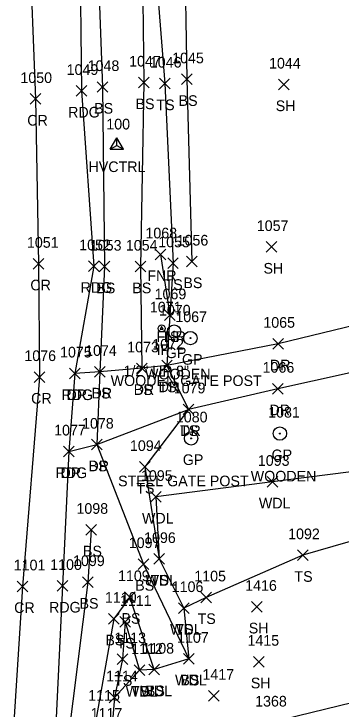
# Model space of a CAD drawing. Extents: x 1678553 to 1680768, y 787260 to 792325.
# Drawn here: x 1678701.2 to 1678762.7, y 787588.2 to 787718.8 of the extents above; entities that cross this region are included whole.
import ezdxf

# ---------------------------------------------------------------- set-up
doc = ezdxf.new("R2010")
doc.units = 0
for name, color, linetype in [('C_A', 7, 'Continuous'), ('C_I', 7, 'Continuous'), ('CPSM', 7, 'Continuous'), ('L_A', 7, 'Continuous'), ('L_I', 7, 'Continuous'), ('L_TIC', 7, 'Continuous'), ('LAWA', 7, 'Continuous'), ('LAWE', 7, 'Continuous'), ('LELB', 7, 'Continuous'), ('LFNC', 7, 'Continuous'), ('M_A', 7, 'Continuous'), ('M_C', 7, 'Continuous'), ('M_I', 7, 'Continuous'), ('MPIR', 7, 'Continuous'), ('P_A', 7, 'Continuous'), ('P_I', 7, 'Continuous'), ('P_TIC', 7, 'Continuous'), ('PEU', 7, 'Continuous'), ('PRC', 7, 'Continuous'), ('R_A', 7, 'Continuous'), ('R_C', 7, 'Continuous'), ('R_I', 7, 'Continuous'), ('R_TIC', 7, 'Continuous'), ('RDP', 7, 'Continuous'), ('RGP', 7, 'Continuous')]:
    doc.layers.add(name, color=color, linetype=linetype)

msp = doc.modelspace()

# ---------------------------------------------------------------- linework, layer by layer
at = {"layer": 'CPSM'}
for p, q in [((1678719.31, 787693.37), (1678720.56, 787695.53)), ((1678721.81, 787693.37), (1678720.56, 787695.53)), ((1678720.56, 787694.09), (1678720.56, 787695.53)), ((1678719.31, 787693.37), (1678720.56, 787694.09)), ((1678719.31, 787693.37), (1678721.81, 787693.37)), ((1678720.56, 787694.09), (1678720.56, 787694.09)), ((1678720.56, 787694.09), (1678721.81, 787693.37))]:
    msp.add_line(p, q, dxfattribs=at)
at = {"layer": 'L_TIC'}
for points in [[(1678724.65, 787704.9), (1678726.65, 787706.9)], [(1678726.65, 787704.9), (1678724.65, 787706.9)], [(1678728.61, 787704.71), (1678730.61, 787706.71)], [(1678730.61, 787704.71), (1678728.61, 787706.71)], [(1678732.74, 787705.51), (1678734.74, 787707.51)], [(1678734.74, 787705.51), (1678732.74, 787707.51)], [(1678750.94, 787704.53), (1678752.94, 787706.53)], [(1678752.94, 787704.53), (1678750.94, 787706.53)], [(1678716.88, 787704.06), (1678718.88, 787706.06)], [(1678718.88, 787704.06), (1678716.88, 787706.06)], [(1678748.64, 787674.02), (1678750.64, 787676.02)], [(1678750.64, 787674.02), (1678748.64, 787676.02)], [(1678727.77, 787672.63), (1678729.77, 787674.63)], [(1678729.77, 787672.63), (1678727.77, 787674.63)], [(1678730.13, 787670.96), (1678732.13, 787672.96)], [(1678732.13, 787670.96), (1678730.13, 787672.96)], [(1678733.64, 787671.29), (1678735.64, 787673.29)], [(1678735.64, 787671.29), (1678733.64, 787673.29)], [(1678717.28, 787670.33), (1678719.28, 787672.33)], [(1678719.28, 787670.33), (1678717.28, 787672.33)], [(1678724.04, 787670.33), (1678726.04, 787672.33)], [(1678726.04, 787670.33), (1678724.04, 787672.33)], [(1678729.51, 787661.19), (1678731.51, 787663.19)], [(1678731.51, 787661.19), (1678729.51, 787663.19)], [(1678729.51, 787661.19), (1678731.51, 787663.19)], [(1678731.51, 787661.19), (1678729.51, 787663.19)], [(1678724.3, 787651.23), (1678726.3, 787653.23)], [(1678726.3, 787651.23), (1678724.3, 787653.23)], [(1678729, 787651.74), (1678731, 787653.74)], [(1678731, 787651.74), (1678729, 787653.74)], [(1678716.39, 787650.57), (1678718.39, 787652.57)], [(1678718.39, 787650.57), (1678716.39, 787652.57)], [(1678733.05, 787643.53), (1678735.05, 787645.53)], [(1678735.05, 787643.53), (1678733.05, 787645.53)], [(1678715.82, 787636.9), (1678717.82, 787638.9)], [(1678717.82, 787636.9), (1678715.82, 787638.9)], [(1678724.82, 787632.71), (1678726.82, 787634.71)], [(1678726.82, 787632.71), (1678724.82, 787634.71)], [(1678748.84, 787629.92), (1678750.84, 787631.92)], [(1678750.84, 787629.92), (1678748.84, 787631.92)], [(1678726.88, 787627.09), (1678728.88, 787629.09)], [(1678728.88, 787627.09), (1678726.88, 787629.09)], [(1678714.77, 787620.91), (1678716.77, 787622.91)], [(1678716.77, 787620.91), (1678714.77, 787622.91)], [(1678754.53, 787616.14), (1678756.53, 787618.14)], [(1678756.53, 787616.14), (1678754.53, 787618.14)], [(1678724.59, 787614.48), (1678726.59, 787616.48)], [(1678726.59, 787614.48), (1678724.59, 787616.48)], [(1678724.59, 787614.48), (1678726.59, 787616.48)], [(1678726.59, 787614.48), (1678724.59, 787616.48)], [(1678727.53, 787615.43), (1678729.53, 787617.43)], [(1678729.53, 787615.43), (1678727.53, 787617.43)], [(1678727.53, 787615.43), (1678729.53, 787617.43)], [(1678729.53, 787615.43), (1678727.53, 787617.43)], [(1678714.13, 787611.1), (1678716.13, 787613.1)], [(1678716.13, 787611.1), (1678714.13, 787613.1)], [(1678722.01, 787608.27), (1678724.01, 787610.27)], [(1678724.01, 787608.27), (1678722.01, 787610.27)], [(1678736.34, 787608.22), (1678738.34, 787610.22)], [(1678738.34, 787608.22), (1678736.34, 787610.22)], [(1678745.87, 787606.45), (1678747.87, 787608.45)], [(1678747.87, 787606.45), (1678745.87, 787608.45)], [(1678732.15, 787606.22), (1678734.15, 787608.22)], [(1678734.15, 787606.22), (1678732.15, 787608.22)], [(1678732.15, 787606.22), (1678734.15, 787608.22)], [(1678734.15, 787606.22), (1678732.15, 787608.22)], [(1678718.99, 787604.2), (1678720.99, 787606.2)], [(1678720.99, 787604.2), (1678718.99, 787606.2)], [(1678721.14, 787603.62), (1678723.14, 787605.62)], [(1678723.14, 787603.62), (1678721.14, 787605.62)], [(1678721.14, 787603.62), (1678723.14, 787605.62)], [(1678723.14, 787603.62), (1678721.14, 787605.62)], [(1678720.67, 787596.62), (1678722.67, 787598.62)], [(1678722.67, 787596.62), (1678720.67, 787598.62)], [(1678733.09, 787596.69), (1678735.09, 787598.69)], [(1678735.09, 787596.69), (1678733.09, 787598.69)], [(1678733.09, 787596.69), (1678735.09, 787598.69)], [(1678735.09, 787596.69), (1678733.09, 787598.69)], [(1678746.25, 787596.14), (1678748.25, 787598.14)], [(1678748.25, 787596.14), (1678746.25, 787598.14)], [(1678723.83, 787594.57), (1678725.83, 787596.57)], [(1678725.83, 787594.57), (1678723.83, 787596.57)], [(1678723.83, 787594.57), (1678725.83, 787596.57)], [(1678725.83, 787594.57), (1678723.83, 787596.57)], [(1678726.59, 787594.66), (1678728.59, 787596.66)], [(1678728.59, 787594.66), (1678726.59, 787596.66)], [(1678726.59, 787594.66), (1678728.59, 787596.66)], [(1678728.59, 787594.66), (1678726.59, 787596.66)], [(1678737.79, 787589.75), (1678739.79, 787591.75)], [(1678739.79, 787589.75), (1678737.79, 787591.75)], [(1678719.12, 787589.44), (1678721.12, 787591.44)], [(1678721.12, 787589.44), (1678719.12, 787591.44)], [(1678719.12, 787589.44), (1678721.12, 787591.44)], [(1678721.12, 787589.44), (1678719.12, 787591.44)]]:
    msp.add_lwpolyline(points, dxfattribs=at)
at = {"layer": 'LAWA'}
msp.add_lwpolyline([(1678789.66, 787618.55), (1678782.28, 787633.91), (1678770.99, 787633.61), (1678749.84, 787630.92), (1678727.88, 787628.09), (1678728.53, 787616.43), (1678733.15, 787607.22), (1678734.09, 787597.69), (1678727.59, 787595.66), (1678724.83, 787595.57), (1678720.12, 787590.44), (1678719.43, 787582.2)], dxfattribs=at)
at = {"layer": 'LAWE'}
msp.add_lwpolyline([(1678722.67, 787582.69), (1678729.64, 787581.87), (1678749.3, 787585.72), (1678767.55, 787590.14), (1678784.53, 787599.95), (1678818.4, 787617.01)], dxfattribs=at)
at = {"layer": 'LELB'}
for points in [[(1678709.4, 787836.24), (1678712.41, 787802.3), (1678715.2, 787769.05), (1678716.9, 787732.18), (1678717.88, 787705.06), (1678718.28, 787671.33), (1678717.39, 787651.57), (1678716.82, 787637.9), (1678725.59, 787615.48)], [(1678711.45, 787836.11), (1678718.36, 787803.19), (1678726.6, 787769.62), (1678727.53, 787731.61), (1678729.61, 787705.71), (1678731.13, 787671.96), (1678730.51, 787662.19), (1678730, 787652.74), (1678734.05, 787644.53), (1678725.82, 787633.71), (1678728.53, 787616.43)], [(1678717.2, 787799.09), (1678720.39, 787781.96), (1678724.18, 787769.78), (1678725.32, 787731.66), (1678725.65, 787705.9), (1678725.04, 787671.33), (1678725.3, 787652.23)], [(1678731.19, 787767.04), (1678733.28, 787732.25), (1678733.74, 787706.51), (1678734.64, 787672.29)], [(1678817.97, 787629.35), (1678796.25, 787621.01), (1678789.66, 787618.55), (1678772.84, 787622.13), (1678755.53, 787617.14), (1678737.34, 787609.22), (1678733.15, 787607.22)], [(1678715.77, 787621.91), (1678715.13, 787612.1), (1678711.4, 787582.3), (1678709.58, 787571.68), (1678707.82, 787563.26)], [(1678725.59, 787615.48), (1678734.09, 787597.69)], [(1678727.59, 787595.66), (1678723.01, 787609.27), (1678719.99, 787605.2), (1678716.76, 787586.82), (1678717.22, 787583.43), (1678719.43, 787582.2)], [(1678722.14, 787604.62), (1678721.67, 787597.62), (1678720.12, 787590.44)], [(1678722.14, 787604.62), (1678724.83, 787595.57)]]:
    msp.add_lwpolyline(points, dxfattribs=at)
at = {"layer": 'LFNC'}
msp.add_lwpolyline([(1678728.77, 787673.63), (1678730.51, 787662.19)], dxfattribs=at)
at = {"layer": 'MPIR'}
msp.add_lwpolyline([(1678728.99, 787660.06), (1678728.7, 787659.56), (1678729.28, 787659.56)], close=True, dxfattribs=at)
msp.add_circle((1678728.99, 787659.73), 0.667, dxfattribs=at)
at = {"layer": 'P_TIC'}
for points in [[(1678712.93, 787703.33), (1678714.93, 787705.33)], [(1678714.93, 787703.33), (1678712.93, 787705.33)], [(1678704.32, 787701.81), (1678706.32, 787703.81)], [(1678706.32, 787701.81), (1678704.32, 787703.81)], [(1678704.89, 787670.87), (1678706.89, 787672.87)], [(1678706.89, 787670.87), (1678704.89, 787672.87)], [(1678715.28, 787670.41), (1678717.28, 787672.41)], [(1678717.28, 787670.41), (1678715.28, 787672.41)], [(1678705.04, 787649.6), (1678707.04, 787651.6)], [(1678707.04, 787649.6), (1678705.04, 787651.6)], [(1678711.68, 787650.27), (1678713.68, 787652.27)], [(1678713.68, 787650.27), (1678711.68, 787652.27)], [(1678710.57, 787635.62), (1678712.57, 787637.62)], [(1678712.57, 787635.62), (1678710.57, 787637.62)], [(1678709.35, 787610.37), (1678711.35, 787612.37)], [(1678711.35, 787610.37), (1678709.35, 787612.37)], [(1678701.84, 787610.29), (1678703.84, 787612.29)], [(1678703.84, 787610.29), (1678701.84, 787612.29)]]:
    msp.add_lwpolyline(points, dxfattribs=at)
at = {"layer": 'PEU'}
msp.add_lwpolyline([(1678707.07, 787835.6), (1678708.87, 787801.61), (1678711.16, 787769.03), (1678713.63, 787732.08), (1678713.93, 787704.33), (1678716.28, 787671.41), (1678712.68, 787651.27), (1678711.57, 787636.62), (1678710.35, 787611.37), (1678708.98, 787582.71), (1678707.82, 787563.26), (1678700.14, 787562.55), (1678691.17, 787560.92)], dxfattribs=at)
at = {"layer": 'PRC'}
msp.add_lwpolyline([(1678698.82, 787835.52), (1678700.15, 787799.39), (1678701.73, 787769.29), (1678704.12, 787733.19), (1678705.32, 787702.81), (1678705.89, 787671.87), (1678706.04, 787650.6), (1678702.84, 787611.29), (1678700.91, 787580.88), (1678700.14, 787562.55)], dxfattribs=at)
at = {"layer": 'R_TIC'}
for points in [[(1678749.91, 787655.85), (1678751.91, 787657.85)], [(1678751.91, 787655.85), (1678749.91, 787657.85)], [(1678724.3, 787651.23), (1678726.3, 787653.23)], [(1678726.3, 787651.23), (1678724.3, 787653.23)], [(1678729, 787651.74), (1678731, 787653.74)], [(1678731, 787651.74), (1678729, 787653.74)], [(1678711.68, 787650.27), (1678713.68, 787652.27)], [(1678713.68, 787650.27), (1678711.68, 787652.27)], [(1678716.39, 787650.57), (1678718.39, 787652.57)], [(1678718.39, 787650.57), (1678716.39, 787652.57)], [(1678749.83, 787647.41), (1678751.83, 787649.41)], [(1678751.83, 787647.41), (1678749.83, 787649.41)], [(1678733.05, 787643.53), (1678735.05, 787645.53)], [(1678735.05, 787643.53), (1678733.05, 787645.53)], [(1678733.05, 787643.53), (1678735.05, 787645.53)], [(1678735.05, 787643.53), (1678733.05, 787645.53)], [(1678715.82, 787636.9), (1678717.82, 787638.9)], [(1678717.82, 787636.9), (1678715.82, 787638.9)], [(1678710.57, 787635.62), (1678712.57, 787637.62)], [(1678712.57, 787635.62), (1678710.57, 787637.62)]]:
    msp.add_lwpolyline(points, dxfattribs=at)
at = {"layer": 'RDP'}
for points in [[(1678806.83, 787669.51), (1678782.39, 787664.49), (1678750.91, 787656.85), (1678730, 787652.74), (1678725.3, 787652.23), (1678717.39, 787651.57), (1678712.68, 787651.27)], [(1678810.64, 787662.52), (1678784.51, 787655.8), (1678750.83, 787648.41), (1678734.05, 787644.53)], [(1678711.57, 787636.62), (1678716.82, 787637.9), (1678734.05, 787644.53)]]:
    msp.add_lwpolyline(points, dxfattribs=at)
at = {"layer": 'RGP'}
for p, q in [((1678731.34, 787659.15), (1678731.34, 787659.15)), ((1678734.39, 787657.91), (1678734.39, 787657.91)), ((1678751.21, 787639.98), (1678751.21, 787639.98)), ((1678734.53, 787639.08), (1678734.53, 787639.08))]:
    msp.add_line(p, q, dxfattribs=at)
for centre, radius in [((1678731.34, 787659.15), 1.25), ((1678731.34, 787659.15), 0.0833), ((1678734.39, 787657.91), 1.25), ((1678734.39, 787657.91), 0.0833), ((1678751.21, 787639.98), 1.25), ((1678734.53, 787639.08), 1.25), ((1678751.21, 787639.98), 0.0833), ((1678734.53, 787639.08), 0.0833)]:
    msp.add_circle(centre, radius, dxfattribs=at)

# ---------------------------------------------------------------- texts
at = {"layer": 'C_A'}
msp.add_text('HVCTRL', height=2, dxfattribs=at).set_placement((1678715.26, 787689.09))
at = {"layer": 'C_I'}
msp.add_text('100', height=2, dxfattribs=at).set_placement((1678718.6, 787697.09))
at = {"layer": 'L_A'}
for s, p in [('BS', (1678724.09, 787700.9)), ('TS', (1678728.02, 787700.71)), ('BS', (1678732.18, 787701.51)), ('SH', (1678750.43, 787700.53)), ('BS', (1678716.32, 787700.06)), ('SH', (1678748.13, 787670.02)), ('FNR', (1678726.31, 787668.63)), ('TS', (1678729.54, 787666.96)), ('BS', (1678733.08, 787667.29)), ('BS', (1678716.72, 787666.33)), ('BS', (1678723.48, 787666.33)), ('FNR', (1678728.04, 787657.19)), ('TS', (1678728.92, 787657.19)), ('BS', (1678723.74, 787647.23)), ('TS', (1678728.41, 787647.74)), ('BS', (1678715.83, 787646.57)), ('TS', (1678732.46, 787639.53)), ('BS', (1678715.26, 787632.9)), ('TS', (1678724.23, 787628.71)), ('WDL', (1678747.26, 787625.92)), ('WDL', (1678725.3, 787623.09)), ('BS', (1678714.21, 787616.91)), ('TS', (1678753.94, 787612.14)), ('BS', (1678724.03, 787610.48)), ('BS', (1678724.03, 787610.48)), ('WDL', (1678725.95, 787611.43)), ('TS', (1678726.94, 787611.43)), ('BS', (1678713.57, 787607.1)), ('BS', (1678721.45, 787604.27)), ('TS', (1678735.75, 787604.22)), ('WDL', (1678730.57, 787602.22)), ('TS', (1678731.56, 787602.22)), ('SH', (1678745.36, 787602.45)), ('BS', (1678718.43, 787600.2)), ('TS', (1678720.55, 787599.62)), ('TS', (1678720.55, 787599.62)), ('TS', (1678720.08, 787592.62)), ('WDL', (1678731.51, 787592.69)), ('BS', (1678732.53, 787592.69)), ('SH', (1678745.74, 787592.14)), ('WDL', (1678722.25, 787590.57)), ('TS', (1678723.24, 787590.57)), ('WDL', (1678725, 787590.66)), ('BS', (1678726.03, 787590.66))]:
    msp.add_text(s, height=2, dxfattribs=at).set_placement(p)
at = {"layer": 'L_I'}
for s, p in [('1047', (1678722.88, 787708.9)), ('1046', (1678726.78, 787708.71)), ('1045', (1678730.97, 787709.51)), ('1044', (1678749.17, 787708.53)), ('1048', (1678715.1, 787708.06)), ('1057', (1678746.87, 787678.02)), ('1068', (1678725.95, 787676.63)), ('1053', (1678715.51, 787674.33)), ('1054', (1678722.27, 787674.33)), ('1055', (1678728.36, 787674.96)), ('1056', (1678731.81, 787675.29)), ('1069', (1678727.68, 787665.19)), ('1069', (1678727.68, 787665.19)), ('1073', (1678722.53, 787655.23)), ('1072', (1678727.23, 787655.74)), ('1074', (1678714.62, 787654.57)), ('1079', (1678731.27, 787647.53)), ('1078', (1678714.05, 787640.9)), ('1094', (1678723.04, 787636.71)), ('1093', (1678747.07, 787633.92)), ('1095', (1678725.11, 787631.09)), ('1098', (1678712.99, 787624.91)), ('1092', (1678752.76, 787620.14)), ('1097', (1678722.82, 787618.48)), ('1097', (1678722.82, 787618.48)), ('1096', (1678725.7, 787619.43)), ('1096', (1678725.7, 787619.43)), ('1099', (1678712.35, 787615.1)), ('1109', (1678720.8, 787612.27)), ('1105', (1678735.13, 787612.22)), ('1416', (1678744.69, 787610.45)), ('1106', (1678730.89, 787610.22)), ('1106', (1678730.89, 787610.22)), ('1110', (1678718.34, 787608.2)), ('1111', (1678721.15, 787607.62)), ('1111', (1678721.15, 787607.62)), ('1113', (1678720.12, 787600.62)), ('1107', (1678731.89, 787600.69)), ('1107', (1678731.89, 787600.69)), ('1415', (1678745.12, 787600.14)), ('1108', (1678725.38, 787598.66)), ('1108', (1678725.38, 787598.66)), ('1112', (1678723.27, 787598.57)), ('1112', (1678723.27, 787598.57)), ('1114', (1678718.56, 787593.44)), ('1114', (1678718.56, 787593.44)), ('1417', (1678736.66, 787593.75)), ('1115', (1678715.2, 787589.82)), ('1368', (1678746.56, 787588.72)), ('1117', (1678715.66, 787586.43))]:
    msp.add_text(s, height=2, dxfattribs=at).set_placement(p)
at = {"layer": 'M_A'}
msp.add_text('IP', height=2, dxfattribs=at).set_placement((1678728.04, 787654.73))
at = {"layer": 'M_C'}
msp.add_text('1/2" UP 8"', height=2, dxfattribs=at).set_placement((1678721.83, 787650.73))
at = {"layer": 'M_I'}
msp.add_text('1071', height=2, dxfattribs=at).set_placement((1678726.79, 787662.73))
at = {"layer": 'P_A'}
for s, p in [('RDG', (1678711.42, 787699.33)), ('CR', (1678703.75, 787697.81)), ('CR', (1678704.33, 787666.87)), ('RDG', (1678713.77, 787666.41)), ('CR', (1678704.47, 787645.6)), ('RDG', (1678710.17, 787646.27)), ('RDG', (1678709.06, 787631.62)), ('CR', (1678701.28, 787606.29)), ('RDG', (1678707.84, 787606.37))]:
    msp.add_text(s, height=2, dxfattribs=at).set_placement(p)
at = {"layer": 'P_I'}
for s, p in [('1049', (1678711.15, 787707.33)), ('1050', (1678702.46, 787705.81)), ('1051', (1678703.69, 787674.87)), ('1052', (1678713.51, 787674.41)), ('1076', (1678703.21, 787653.6)), ('1075', (1678709.91, 787654.27)), ('1077', (1678708.8, 787639.62)), ('1101', (1678701.21, 787614.29)), ('1100', (1678708.06, 787614.37))]:
    msp.add_text(s, height=2, dxfattribs=at).set_placement(p)
at = {"layer": 'R_A'}
for s, p in [('GP', (1678729.78, 787654.15)), ('GP', (1678732.82, 787652.91)), ('DR', (1678749.35, 787651.85)), ('DR', (1678723.74, 787647.23)), ('DR', (1678728.43, 787647.74)), ('DR', (1678711.12, 787646.27)), ('DR', (1678715.82, 787646.57)), ('DR', (1678749.26, 787643.41)), ('DR', (1678732.49, 787639.53)), ('DR', (1678732.49, 787639.53)), ('GP', (1678732.97, 787634.08)), ('GP', (1678749.65, 787634.98)), ('DR', (1678715.25, 787632.9)), ('DR', (1678710, 787631.62))]:
    msp.add_text(s, height=2, dxfattribs=at).set_placement(p)
at = {"layer": 'R_C'}
for s, p in [('WOODEN', (1678725.86, 787650.15)), ('WOODEN GATE POST', (1678719.42, 787648.91)), ('STEEL GATE POST', (1678720.81, 787630.08)), ('WOODEN', (1678745.73, 787630.98))]:
    msp.add_text(s, height=2, dxfattribs=at).set_placement(p)
at = {"layer": 'R_I'}
for s, p in [('1070', (1678728.49, 787662.15)), ('1067', (1678731.57, 787660.91)), ('1065', (1678748.1, 787659.85)), ('1073', (1678722.53, 787655.23)), ('1072', (1678727.23, 787655.74)), ('1075', (1678709.91, 787654.27)), ('1074', (1678714.62, 787654.57)), ('1066', (1678747.96, 787651.41)), ('1079', (1678731.27, 787647.53)), ('1079', (1678731.27, 787647.53)), ('1081', (1678749.01, 787642.98)), ('1080', (1678731.67, 787642.08)), ('1078', (1678714.05, 787640.9)), ('1077', (1678708.8, 787639.62)), ('1115', (1678715.2, 787589.82))]:
    msp.add_text(s, height=2, dxfattribs=at).set_placement(p)

doc.saveas('drawing.dxf')
